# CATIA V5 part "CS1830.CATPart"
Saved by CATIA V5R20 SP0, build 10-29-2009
Part number: CS1830
Revision: 4
Definition: design
Nomenclature: CS1830
Source: made
Description: NOT SPECIFIED
Bounding box of the stored display mesh (mm): x -29 to 29, y -29 to 29, z -55 to 15
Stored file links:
  C:\Users\Raffaele\Desktop\3D X SITO CF\BOLEX\20-TILTED COLUMN SUPPORT\CS1830.CATPart
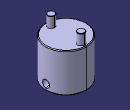
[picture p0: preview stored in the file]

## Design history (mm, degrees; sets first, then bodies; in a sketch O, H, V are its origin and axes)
Body1 "MANIFOLD_SOLID_BREP #715" (main body)
  Solid1: solid without history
